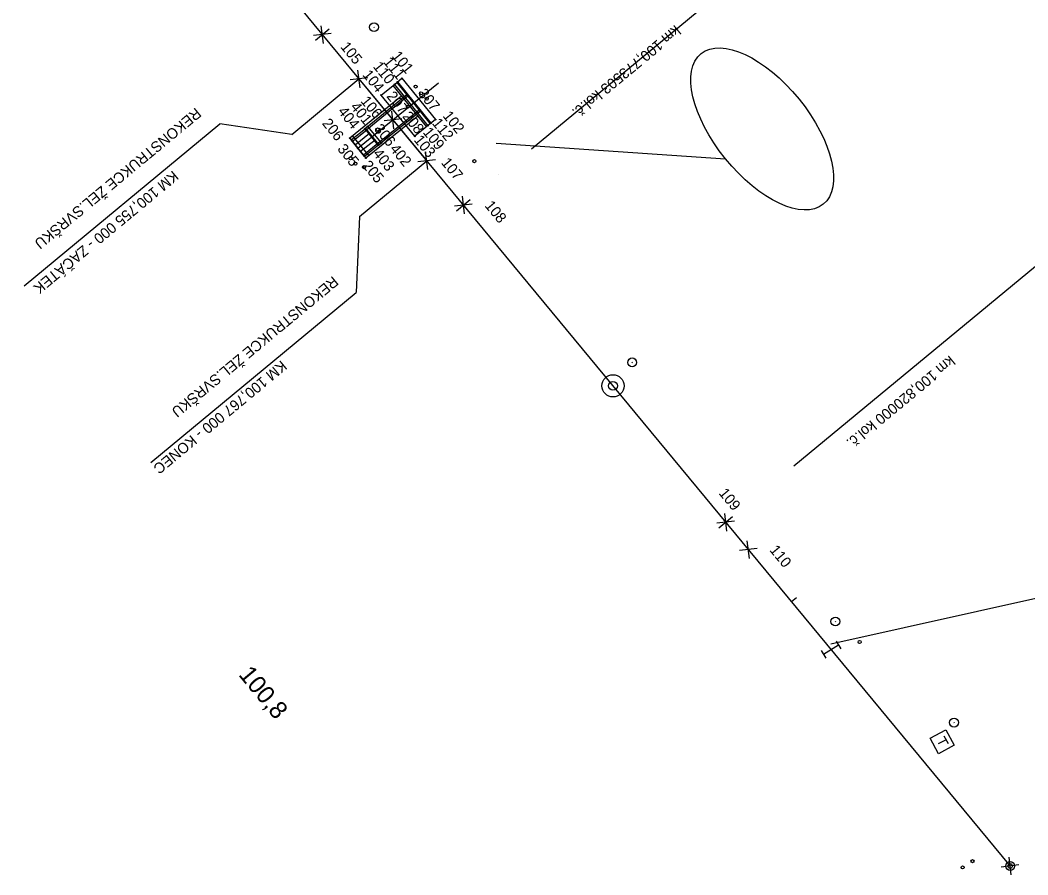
# Model space of a CAD drawing. Extents: x -505028 to -503155, y -1080361 to -1077947.
# Drawn here: x -504529.5 to -504415.6, y -1078869.1 to -1078772.6 of the extents above; entities that cross this region are included whole.
import ezdxf

# ---------------------------------------------------------------- set-up
doc = ezdxf.new("R2010")
doc.units = 0
for name, color, linetype in [('12_vytyceni', 7, 'Continuous'), ('bublinySOPS', 7, 'Continuous'), ('C3D-BOD', 7, 'Continuous'), ('C3D-TRASA-POPIS', 7, 'Continuous'), ('C3D_Povrch - Popis', 7, 'Continuous'), ('C3D_Trasa-Popisy trasy', 7, 'Continuous'), ('Default', 7, 'Continuous'), ('Drobná stavba - strom_1', 7, 'Continuous'), ('Návěst místo trati_1', 7, 'Continuous'), ('Sdělovací objekt', 7, 'Continuous'), ('SO01 NS_tlustá plná', 7, 'Continuous'), ('SO01_NS_tenká čárkovaná_základy', 7, 'Continuous'), ('SO01_NS_tlustá čárkovaná_trouby', 7, 'Continuous'), ('SO01_tenká čerchovaná_osy_zábradlí', 7, 'Continuous'), ('SO01_velmi tlustá_římsy', 7, 'Continuous'), ('SO021701 popisky', 7, 'Continuous'), ('Svršek součást_1', 7, 'Continuous'), ('Teplo nadzemní_1', 7, 'Continuous'), ('Trasa-Geometrie', 7, 'Continuous'), ('Vrstva 24', 7, 'Continuous'), ('Vrstva 27', 7, 'Continuous'), ('Vrstva 3', 7, 'Continuous'), ('Vrstva 33', 7, 'Continuous'), ('Vrstva 50', 7, 'Continuous'), ('Vrstva 7', 7, 'Continuous'), ('ŽKN stavba druh', 7, 'Continuous')]:
    doc.layers.add(name, color=color, linetype=linetype)

# ---------------------------------------------------------------- blocks, each defined once
blk = doc.blocks.new('C649_8')
at = {"layer": 'Svršek součást_1'}
for p, q in [((-3.6, 10.6), (6.4, 9.2)), ((1.4, 9.9), (-1.4, -9.9)), ((-6.3, -9.2), (3.6, -10.6))]:
    blk.add_line(p, q, dxfattribs=at)
blk = doc.blocks.new('C535_1')
at = {"layer": 'Sdělovací objekt'}
for p, q in [((-4, 5.8), (5.8, 4)), ((1, 4.9), (-1, -4.9))]:
    blk.add_line(p, q, dxfattribs=at)
blk.add_lwpolyline([(-8, 11.7), (11.7, 8), (8, -11.7), (-11.7, -8), (-8, 11.7)], dxfattribs=at)
blk = doc.blocks.new('C053_20')
at = {"layer": 'Drobná stavba - strom_1'}
blk.add_line((-0.5, 0), (0.5, 0), dxfattribs=at)
blk.add_circle((0, 0), 5, dxfattribs=at)
blk = doc.blocks.new('C053_19')
at = {"layer": 'Teplo nadzemní_1'}
blk.add_line((-0.5, 0), (0.5, 0), dxfattribs=at)
blk.add_circle((0, 0), 5, dxfattribs=at)
blk = doc.blocks.new('C045')
at = {"layer": 'ŽKN stavba druh'}
blk.add_circle((0, 0), 1.75, dxfattribs=at)
blk = doc.blocks.new('popiska_hektometr_sit')
at = {"layer": 'Default'}
blk.add_circle((0, 0), 10, dxfattribs=at)
blk = doc.blocks.new('AeccTickCircle')
at = {"layer": 'Default'}
blk.add_circle((0, 0), 5, dxfattribs=at)
blk = doc.blocks.new('_kolecko-HB')
at = {"layer": 'Default'}
blk.add_circle((0, 0.02), 5, dxfattribs=at)
blk = doc.blocks.new('_U970')
at = {"layer": 'Default'}
for p, q in [((-7.1, -7.1), (7.1, 7.1)), ((-7.1, 7.1), (7.1, -7.1))]:
    blk.add_line(p, q, dxfattribs=at)
blk = doc.blocks.new('_U5866')
at = {"layer": 'Default'}
blk.add_ellipse((0, 10.71), major_axis=(21.91, 0), ratio=0.488871, dxfattribs=at)
blk = doc.blocks.new('C093_5')
at = {"layer": 'Návěst místo trati_1'}
blk.add_line((-0.5, 0), (0.5, 0), dxfattribs=at)
blk.add_circle((0, 0), 5, dxfattribs=at)

msp = doc.modelspace()

# ---------------------------------------------------------------- linework, layer by layer
at = {"layer": '12_vytyceni'}
for centre in [(-504486.36, -1078779.13), (-504487.21, -1078779.82), (-504486.86, -1078779.54), (-504488.69, -1078781.02), (-504486.39, -1078781.15), (-504485.05, -1078781.93), (-504484.57, -1078783.4), (-504482.58, -1078783.79), (-504490.55, -1078784.84), (-504490.2, -1078784.56), (-504483.43, -1078784.48), (-504483.08, -1078784.2), (-504492.25, -1078785.9), (-504489.71, -1078785.71), (-504484.91, -1078785.68), (-504491.34, -1078787.03), (-504489.03, -1078786.7), (-504488.68, -1078786.42), (-504490.42, -1078788.15)]:
    msp.add_circle(centre, 0.05, dxfattribs=at)
at = {"layer": 'bublinySOPS'}
for p, q in [((-504475.72, -1078786.46), (-504449.82, -1078788.21)), ((-504437.91, -1078843), (-504405.11, -1078835.7))]:
    msp.add_line(p, q, dxfattribs=at)
at = {"layer": 'C3D_Trasa-Popisy trasy'}
for p, q in [((-504471.71, -1078787.08), (-504425.48, -1078748.83)), ((-504496.12, -1078774.83), (-504494.58, -1078773.55)), ((-504442.07, -1078822.9), (-504395.84, -1078784.66)), ((-504480.18, -1078794.09), (-504478.64, -1078792.81)), ((-504450.55, -1078829.92), (-504449.01, -1078828.64))]:
    msp.add_line(p, q, dxfattribs=at)
at = {"layer": 'Default'}
for p, q in [((-504498.8, -1078785.48), (-504491.21, -1078779.19)), ((-504491.21, -1078779.19), (-504483.56, -1078788.44)), ((-504529.02, -1078802.56), (-504506.93, -1078784.28)), ((-504498.8, -1078785.48), (-504506.93, -1078784.28)), ((-504491.15, -1078794.72), (-504483.56, -1078788.44)), ((-504475.44, -1078790.03), (-504475.46, -1078790.05)), ((-504479.48, -1078793.37), (-504479.48, -1078793.37)), ((-504491.15, -1078794.72), (-504491.52, -1078803.33)), ((-504514.71, -1078822.52), (-504491.52, -1078803.33)), ((-504441.79, -1078837.8), (-504442.35, -1078838.25))]:
    msp.add_line(p, q, dxfattribs=at)
for centre, radius in [((-504487.73, -1078783.4), 0.0105), ((-504449.79, -1078829.29), 0.00462), ((-504417.65, -1078868.11), 0.25)]:
    msp.add_circle(centre, radius, dxfattribs=at)
at = {"layer": 'SO01 NS_tlustá plná'}
for p, q in [((-504486.86, -1078779.54), (-504485.6, -1078781.09)), ((-504492.09, -1078786.09), (-504490.47, -1078784.78)), ((-504491.97, -1078786.25), (-504490.34, -1078784.93)), ((-504490.58, -1078787.96), (-504492.09, -1078786.09)), ((-504491.65, -1078786.64), (-504490.03, -1078785.32)), ((-504489.4, -1078786.1), (-504491.02, -1078787.41)), ((-504489.08, -1078786.49), (-504490.71, -1078787.8)), ((-504488.96, -1078786.64), (-504490.58, -1078787.96))]:
    msp.add_line(p, q, dxfattribs=at)
at = {"layer": 'SO01_NS_tenká čárkovaná_základy'}
for p, q in [((-504487.37, -1078779.95), (-504483.59, -1078784.61)), ((-504486.94, -1078779.6), (-504483.16, -1078784.26)), ((-504486.39, -1078781.15), (-504492.25, -1078785.9)), ((-504484.57, -1078783.4), (-504490.42, -1078788.15)), ((-504492.25, -1078785.9), (-504490.42, -1078788.15)), ((-504491.94, -1078785.65), (-504490.11, -1078787.9))]:
    msp.add_line(p, q, dxfattribs=at)
msp.add_lwpolyline([(-504486.94, -1078779.6), (-504486.36, -1078779.13), (-504482.58, -1078783.79), (-504484.91, -1078785.68), (-504488.69, -1078781.02), (-504486.98, -1078779.63)], dxfattribs=at)
at = {"layer": 'SO01_NS_tlustá čárkovaná_trouby'}
for p, q in [((-504485.81, -1078781), (-504490.47, -1078784.78)), ((-504485.68, -1078781.15), (-504490.34, -1078784.93)), ((-504485.81, -1078781), (-504484.3, -1078782.86)), ((-504484.42, -1078782.71), (-504489.08, -1078786.49)), ((-504484.3, -1078782.86), (-504488.96, -1078786.64)), ((-504490.47, -1078784.78), (-504488.96, -1078786.64))]:
    msp.add_line(p, q, dxfattribs=at)
at = {"layer": 'SO01_tenká čerchovaná_osy_zábradlí'}
msp.add_line((-504491.34, -1078787.03), (-504482.21, -1078779.63), dxfattribs=at)
at = {"layer": 'SO01_velmi tlustá_římsy'}
for p, q in [((-504486.86, -1078779.54), (-504487.21, -1078779.82)), ((-504487.21, -1078779.82), (-504483.43, -1078784.48)), ((-504486.86, -1078779.54), (-504483.08, -1078784.2)), ((-504483.08, -1078784.2), (-504483.43, -1078784.48))]:
    msp.add_line(p, q, dxfattribs=at)
msp.add_lwpolyline([(-504490.55, -1078784.84), (-504489.03, -1078786.7), (-504488.68, -1078786.42), (-504490.2, -1078784.56), (-504490.55, -1078784.84)], dxfattribs=at)
at = {"layer": 'Trasa-Geometrie'}
msp.add_line((-504529.49, -1078732.92), (-504417.65, -1078868.11), dxfattribs=at)

# ---------------------------------------------------------------- block references
at = {"layer": 'bublinySOPS', "xscale": 0.5, "yscale": 0.5, "rotation": 129.01942179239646}
msp.add_blockref('_U5866', (-504441.5, -1078781.47), dxfattribs=at)
at = {"layer": 'C3D-BOD', "xscale": 0.09999999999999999, "yscale": 0.09999999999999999, "rotation": 141.804}
for p in [(-504495.35, -1078774.19), (-504491.21, -1078779.19), (-504487.38, -1078783.82), (-504483.56, -1078788.44), (-504479.41, -1078793.45), (-504449.78, -1078829.28), (-504447.23, -1078832.36), (-504417.65, -1078868.11)]:
    msp.add_blockref('_U970', p, dxfattribs=at)
at = {"layer": 'C3D-TRASA-POPIS', "xscale": 0.10000000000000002, "yscale": 0.10000000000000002, "rotation": -50.400958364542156}
msp.add_blockref('AeccTickCircle', (-504417.65, -1078868.11), dxfattribs=at)
at = {"layer": 'C3D_Trasa-Popisy trasy', "xscale": 0.24999999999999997, "yscale": 0.25, "rotation": -50.40095836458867}
msp.add_blockref('_kolecko-HB', (-504462.52, -1078813.87), dxfattribs=at)
at = {"layer": 'Default', "xscale": 0.05, "yscale": 0.049999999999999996, "rotation": -140.4009583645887}
msp.add_blockref('popiska_hektometr_sit', (-504462.52, -1078813.87), dxfattribs=at)
at = {"layer": 'Vrstva 24', "xscale": 0.1, "yscale": 0.10000000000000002}
for p in [(-504484.81, -1078780.06), (-504484.81, -1078780.06), (-504484.81, -1078780.06), (-504484.81, -1078780.06), (-504484.21, -1078780.83), (-504484.21, -1078780.83), (-504484.21, -1078780.83), (-504484.21, -1078780.83), (-504483.56, -1078781.42), (-504483.56, -1078781.42), (-504483.56, -1078781.42), (-504483.56, -1078781.42), (-504485.67, -1078782.32), (-504485.67, -1078782.32), (-504485.67, -1078782.32), (-504485.67, -1078782.32), (-504489.1, -1078784.91), (-504489.1, -1078784.91), (-504489.1, -1078784.91), (-504489.1, -1078784.91), (-504492.16, -1078788.16), (-504492.16, -1078788.16), (-504492.16, -1078788.16), (-504492.16, -1078788.16), (-504478.17, -1078788.49), (-504478.17, -1078788.49), (-504478.17, -1078788.49), (-504478.17, -1078788.49), (-504491.62, -1078788.77), (-504491.62, -1078788.77), (-504491.62, -1078788.77), (-504491.62, -1078788.77), (-504490.65, -1078789.17), (-504490.65, -1078789.17), (-504490.65, -1078789.17), (-504490.65, -1078789.17), (-504434.65, -1078842.81), (-504434.65, -1078842.81), (-504434.65, -1078842.81), (-504434.65, -1078842.81), (-504423.02, -1078868.27), (-504423.02, -1078868.27), (-504423.02, -1078868.27), (-504423.02, -1078868.27), (-504421.9, -1078867.56), (-504421.9, -1078867.56), (-504421.9, -1078867.56), (-504421.9, -1078867.56)]:
    msp.add_blockref('C045', p, dxfattribs=at)
at = {"layer": 'Vrstva 27', "xscale": 0.09999999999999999, "yscale": 0.1, "rotation": -54.381065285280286}
msp.add_blockref('C053_19', (-504437.39, -1078840.49), dxfattribs=at)
msp.add_blockref('C053_19', (-504437.39, -1078840.49), dxfattribs=at)
msp.add_blockref('C053_19', (-504437.39, -1078840.49), dxfattribs=at)
msp.add_blockref('C053_19', (-504437.39, -1078840.49), dxfattribs=at)
at = {"layer": 'Vrstva 3', "xscale": 0.1, "yscale": 0.09999999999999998, "rotation": -50.41345363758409}
msp.add_blockref('C649_8', (-504437.9, -1078843.68), dxfattribs=at)
msp.add_blockref('C649_8', (-504437.9, -1078843.68), dxfattribs=at)
msp.add_blockref('C649_8', (-504437.9, -1078843.68), dxfattribs=at)
msp.add_blockref('C649_8', (-504437.9, -1078843.68), dxfattribs=at)
at = {"layer": 'Vrstva 33', "xscale": 0.1, "yscale": 0.10000000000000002, "rotation": -50.8292257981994}
msp.add_blockref('C535_1', (-504425.33, -1078854.07), dxfattribs=at)
msp.add_blockref('C535_1', (-504425.33, -1078854.07), dxfattribs=at)
msp.add_blockref('C535_1', (-504425.33, -1078854.07), dxfattribs=at)
msp.add_blockref('C535_1', (-504425.33, -1078854.07), dxfattribs=at)
at = {"layer": 'Vrstva 50', "yscale": 0.1}
for p, xscale, rotation in [((-504489.51, -1078773.35), 0.10000000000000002, -52.44904289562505), ((-504489.51, -1078773.35), 0.10000000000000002, -52.44904289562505), ((-504423.99, -1078851.91), 0.09999999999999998, -50.522981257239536), ((-504423.99, -1078851.91), 0.09999999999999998, -50.522981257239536)]:
    msp.add_blockref('C053_20', p, dxfattribs=dict(at, xscale=xscale, rotation=rotation))
at = {"layer": 'Vrstva 7', "xscale": 0.09999999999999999, "yscale": 0.1, "rotation": -51.02970449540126}
msp.add_blockref('C093_5', (-504460.35, -1078811.22), dxfattribs=at)
msp.add_blockref('C093_5', (-504460.35, -1078811.22), dxfattribs=at)

# ---------------------------------------------------------------- texts
at = {"layer": '12_vytyceni'}
for s, p in [('111', (-504488.53, -1078777.3)), ('101', (-504487.56, -1078776.64)), ('110', (-504489.69, -1078777.82)), ('104', (-504490.88, -1078778.76)), ('307', (-504484.6, -1078780.88)), ('207', (-504488.16, -1078781.18)), ('404', (-504493.66, -1078782.9)), ('401', (-504492.24, -1078782.39)), ('206', (-504495.44, -1078784.24)), ('208', (-504486.37, -1078783.45)), ('112', (-504483.02, -1078784.22)), ('102', (-504481.81, -1078783.4)), ('306', (-504489.58, -1078784.87)), ('109', (-504484.06, -1078785.25)), ('103', (-504485.07, -1078786.12)), ('305', (-504493.72, -1078787.13)), ('402', (-504487.79, -1078787.13)), ('205', (-504490.91, -1078789)), ('403', (-504489.7, -1078787.67))]:
    msp.add_text(s, height=1.2, rotation=309.0468, dxfattribs=at).set_placement(p)
at = {"layer": 'C3D_Povrch - Popis'}
for s, p in [('105', (-504493.37, -1078775.6)), ('106', (-504491.09, -1078781.73)), ('107', (-504481.99, -1078788.69)), ('108', (-504477.07, -1078793.54)), ('109', (-504450.63, -1078826.02)), ('110', (-504444.89, -1078832.45))]:
    msp.add_text(s, height=1.2, rotation=309.6, dxfattribs=at).set_placement(p)
at = {"layer": 'C3D_Trasa-Popisy trasy'}
for s, height, rotation, p in [('km 100,773503 kol.č. ', 1.2, 219.599, (-504455.51, -1078773.05)), ('km 100,820000 kol.č. ', 1.2, 219.599, (-504424.51, -1078810.37)), ('100,8', 2, 309.599, (-504504.89, -1078846.53))]:
    msp.add_text(s, height=height, rotation=rotation, dxfattribs=at).set_placement(p)
at = {"layer": 'SO021701 popisky'}
for s, p in [('REKONSTRUKCE ŽEL.SVRŠKU', (-504509.66, -1078782.39)), ('KM 100,755 000 - ZAČÁTEK', (-504512.23, -1078789.49)), ('REKONSTRUKCE ŽEL.SVRŠKU', (-504494.17, -1078801.4)), ('KM 100,767 000 - KONEC', (-504499.99, -1078810.93))]:
    msp.add_text(s, height=1.2, rotation=219.6477, dxfattribs=at).set_placement(p)

doc.saveas('drawing.dxf')
